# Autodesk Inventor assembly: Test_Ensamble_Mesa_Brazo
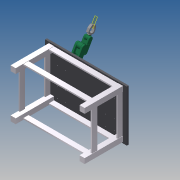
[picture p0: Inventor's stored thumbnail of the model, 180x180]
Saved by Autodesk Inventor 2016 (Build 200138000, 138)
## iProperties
Created: 2015-09
Part Number: Test_Ensamble_Mesa_Brazo
Document SubType Name: Assembly
Designer: julian.chica
Mass: 112992 g
Surface Area: 77559.2 cm^2
Volume: 112992 cm^3
Density: 1 g/cm^3
Author: julian.chica
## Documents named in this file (3)
- C:\Test ExamProfessor 2015\Test_Ensamble_Mesa_Brazo.iam
- C:\Test ExamProfessor 2015\mesa-trabajo.ipt
- C:\Test ExamProfessor 2015\Brazo Mecanico-MOV.iam
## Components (2 placed, 2 different names)
1. mesa-trabajo:1
2. Brazo Mecanico-MOV:1 [sub-assembly]
